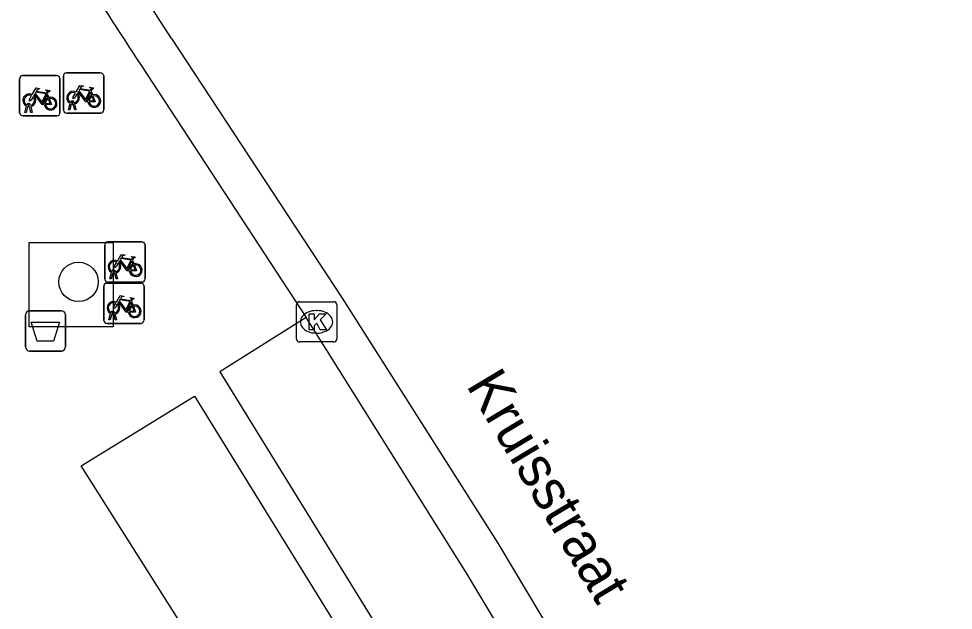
# Model space of a CAD drawing. Extents: x 160379 to 161131, y 383940 to 384849.
# Drawn here: x 161075.69 to 161098.92, y 384397.03 to 384411.72 of the extents above; entities that cross this region are included whole.
import ezdxf

# ---------------------------------------------------------------- set-up
doc = ezdxf.new("R2010")
doc.units = 0
for name, color, linetype in [('IMGEO_Afvalbak', 7, 'Continuous'), ('IMGEO_Boom', 7, 'Continuous'), ('IMGEO_Fietsenrek', 7, 'Continuous'), ('IMGEO_Fietspad_gesloten', 7, 'Continuous'), ('IMGEO_Fietspad_open', 7, 'Continuous'), ('IMGEO_Kolk', 7, 'Continuous'), ('IMGEO_Openbare_ruimte_label', 7, 'Continuous'), ('IMGEO_Voetpad_open', 7, 'Continuous')]:
    doc.layers.add(name, color=color, linetype=linetype)

msp = doc.modelspace()

# ---------------------------------------------------------------- linework, layer by layer
at = {"layer": 'IMGEO_Afvalbak'}
for p, q in [((161075.864, 384403.567), (161075.864, 384404.367)), ((161075.864, 384404.367), (161075.864, 384403.567)), ((161075.964, 384404.467), (161076.754, 384404.467)), ((161076.754, 384404.467), (161075.964, 384404.467)), ((161076.854, 384404.367), (161076.854, 384403.567)), ((161076.854, 384403.567), (161076.854, 384404.367)), ((161076.754, 384403.467), (161075.964, 384403.467)), ((161075.964, 384403.467), (161076.754, 384403.467))]:
    msp.add_line(p, q, dxfattribs=at)
msp.add_lwpolyline([(161076.007, 384404.181), (161076.711, 384404.181), (161076.562, 384403.711), (161076.156, 384403.711), (161076.007, 384404.181)], dxfattribs=at)
for centre, start, end in [((161075.964, 384404.367), 90, 180), ((161075.964, 384404.367), 90, 180), ((161076.754, 384404.367), 0, 90), ((161076.754, 384404.367), 360, 90), ((161075.964, 384403.567), 180, 270), ((161075.964, 384403.567), 180, 270), ((161076.754, 384403.567), 270, 0), ((161076.754, 384403.567), 270, 0)]:
    msp.add_arc(centre, 0.1, start, end, dxfattribs=at)
at = {"layer": 'IMGEO_Boom'}
msp.add_circle((161077.181, 384405.182), 0.489, dxfattribs=at)
at = {"layer": 'IMGEO_Fietsenrek'}
for p, q in [((161075.718, 384409.384), (161075.718, 384410.225)), ((161075.718, 384410.225), (161075.718, 384409.384)), ((161075.793, 384410.309), (161076.634, 384410.309)), ((161076.634, 384410.309), (161075.793, 384410.309)), ((161076.718, 384410.234), (161076.718, 384409.393)), ((161076.718, 384409.393), (161076.718, 384410.234)), ((161076.806, 384409.449), (161076.806, 384410.29)), ((161076.806, 384410.29), (161076.806, 384409.449)), ((161076.881, 384410.374), (161077.722, 384410.374)), ((161077.722, 384410.374), (161076.881, 384410.374)), ((161077.806, 384410.299), (161077.806, 384409.458)), ((161077.806, 384409.458), (161077.806, 384410.299)), ((161077.493, 384409.923), (161077.529, 384409.828)), ((161076.405, 384409.858), (161076.441, 384409.763)), ((161075.845, 384409.393), (161075.884, 384409.553)), ((161075.914, 384409.541), (161075.879, 384409.393)), ((161075.956, 384409.565), (161075.955, 384409.569)), ((161075.997, 384409.393), (161075.963, 384409.535)), ((161075.987, 384409.576), (161075.988, 384409.569)), ((161075.995, 384409.539), (161076.03, 384409.393)), ((161076.933, 384409.458), (161076.972, 384409.618)), ((161076.967, 384409.458), (161076.933, 384409.458)), ((161077.002, 384409.606), (161076.967, 384409.458)), ((161077.044, 384409.63), (161077.043, 384409.634)), ((161077.085, 384409.458), (161077.051, 384409.6)), ((161077.075, 384409.641), (161077.076, 384409.634)), ((161077.083, 384409.604), (161077.118, 384409.458)), ((161077.118, 384409.458), (161077.085, 384409.458)), ((161076.643, 384409.309), (161075.802, 384409.309)), ((161075.802, 384409.309), (161076.643, 384409.309)), ((161075.879, 384409.393), (161075.845, 384409.393)), ((161076.03, 384409.393), (161075.997, 384409.393)), ((161077.731, 384409.374), (161076.89, 384409.374)), ((161076.89, 384409.374), (161077.731, 384409.374)), ((161077.834, 384405.251), (161077.834, 384406.092)), ((161077.834, 384406.092), (161077.834, 384405.251)), ((161077.909, 384406.176), (161078.75, 384406.176)), ((161078.75, 384406.176), (161077.909, 384406.176)), ((161078.834, 384406.101), (161078.834, 384405.26)), ((161078.834, 384405.26), (161078.834, 384406.101)), ((161078.521, 384405.725), (161078.557, 384405.63)), ((161077.961, 384405.26), (161078, 384405.42)), ((161078.03, 384405.408), (161077.995, 384405.26)), ((161078.072, 384405.432), (161078.071, 384405.436)), ((161078.113, 384405.26), (161078.079, 384405.402)), ((161078.103, 384405.443), (161078.104, 384405.436)), ((161078.111, 384405.406), (161078.146, 384405.26)), ((161077.809, 384404.228), (161077.809, 384405.069)), ((161077.809, 384405.069), (161077.809, 384404.228)), ((161077.884, 384405.153), (161078.725, 384405.153)), ((161078.725, 384405.153), (161077.884, 384405.153)), ((161078.759, 384405.176), (161077.918, 384405.176)), ((161077.918, 384405.176), (161078.759, 384405.176)), ((161077.995, 384405.26), (161077.961, 384405.26)), ((161078.146, 384405.26), (161078.113, 384405.26)), ((161078.809, 384405.078), (161078.809, 384404.237)), ((161078.809, 384404.237), (161078.809, 384405.078)), ((161078.496, 384404.702), (161078.532, 384404.607)), ((161077.936, 384404.237), (161077.975, 384404.397)), ((161078.005, 384404.385), (161077.97, 384404.237)), ((161078.047, 384404.409), (161078.046, 384404.413)), ((161078.088, 384404.237), (161078.054, 384404.379)), ((161078.078, 384404.42), (161078.079, 384404.413)), ((161078.086, 384404.383), (161078.121, 384404.237)), ((161078.734, 384404.153), (161077.893, 384404.153)), ((161077.893, 384404.153), (161078.734, 384404.153)), ((161077.97, 384404.237), (161077.936, 384404.237)), ((161078.121, 384404.237), (161078.088, 384404.237))]:
    msp.add_line(p, q, dxfattribs=at)
for points in [[(161076.031, 384409.835), (161076.126, 384409.999), (161076.212, 384409.985), (161076.214, 384409.976), (161076.158, 384409.965), (161076.131, 384409.92), (161076.387, 384409.879)], [(161076.387, 384409.879), (161076.412, 384409.928), (161076.406, 384409.932), (161076.383, 384409.936), (161076.371, 384409.943), (161076.37, 384409.946), (161076.372, 384409.951), (161076.467, 384409.936), (161076.469, 384409.926), (161076.459, 384409.913), (161076.447, 384409.907), (161076.433, 384409.913), (161076.405, 384409.858)], [(161077.119, 384409.9), (161077.214, 384410.064), (161077.3, 384410.05), (161077.302, 384410.041), (161077.246, 384410.03), (161077.219, 384409.985), (161077.475, 384409.944)], [(161077.462, 384409.919), (161077.205, 384409.96), (161077.188, 384409.931), (161077.355, 384409.711), (161077.462, 384409.919)], [(161077.475, 384409.944), (161077.5, 384409.993), (161077.494, 384409.997), (161077.471, 384410.001), (161077.459, 384410.008), (161077.458, 384410.011), (161077.46, 384410.016), (161077.555, 384410.001), (161077.557, 384409.991), (161077.547, 384409.978), (161077.535, 384409.972), (161077.521, 384409.978), (161077.493, 384409.923)], [(161076.052, 384409.783), (161076, 384409.693), (161075.96, 384409.668), (161075.961, 384409.715), (161076.016, 384409.809)], [(161076.327, 384409.591), (161076.277, 384409.591), (161076.086, 384409.842), (161076.067, 384409.81)], [(161076.374, 384409.854), (161076.117, 384409.895), (161076.1, 384409.866), (161076.267, 384409.646), (161076.374, 384409.854)], [(161076.422, 384409.756), (161076.392, 384409.833), (161076.283, 384409.615), (161076.326, 384409.615)], [(161076.356, 384409.615), (161076.476, 384409.614), (161076.432, 384409.728)], [(161076.452, 384409.735), (161076.507, 384409.59), (161076.357, 384409.59)], [(161077.14, 384409.848), (161077.088, 384409.758), (161077.048, 384409.733), (161077.049, 384409.78), (161077.104, 384409.874)], [(161077.415, 384409.656), (161077.365, 384409.656), (161077.174, 384409.907), (161077.155, 384409.875)], [(161077.51, 384409.821), (161077.48, 384409.898), (161077.371, 384409.68), (161077.414, 384409.68)], [(161077.444, 384409.68), (161077.564, 384409.679), (161077.52, 384409.793)], [(161077.54, 384409.8), (161077.595, 384409.655), (161077.445, 384409.655)], [(161078.147, 384405.702), (161078.242, 384405.866), (161078.328, 384405.852), (161078.33, 384405.843), (161078.274, 384405.832), (161078.247, 384405.787), (161078.503, 384405.746)], [(161078.49, 384405.721), (161078.233, 384405.762), (161078.216, 384405.733), (161078.383, 384405.513), (161078.49, 384405.721)], [(161078.503, 384405.746), (161078.528, 384405.795), (161078.522, 384405.799), (161078.499, 384405.803), (161078.487, 384405.81), (161078.486, 384405.813), (161078.488, 384405.818), (161078.583, 384405.803), (161078.585, 384405.793), (161078.575, 384405.78), (161078.563, 384405.774), (161078.549, 384405.78), (161078.521, 384405.725)], [(161078.168, 384405.65), (161078.116, 384405.56), (161078.076, 384405.535), (161078.077, 384405.582), (161078.132, 384405.676)], [(161078.443, 384405.458), (161078.393, 384405.458), (161078.202, 384405.709), (161078.183, 384405.677)], [(161078.538, 384405.623), (161078.508, 384405.7), (161078.399, 384405.482), (161078.442, 384405.482)], [(161078.472, 384405.482), (161078.592, 384405.481), (161078.548, 384405.595)], [(161078.568, 384405.602), (161078.623, 384405.457), (161078.473, 384405.457)], [(161078.122, 384404.679), (161078.217, 384404.843), (161078.303, 384404.829), (161078.305, 384404.82), (161078.249, 384404.809), (161078.222, 384404.764), (161078.478, 384404.723)], [(161078.143, 384404.627), (161078.091, 384404.537), (161078.051, 384404.512), (161078.052, 384404.559), (161078.107, 384404.653)], [(161078.418, 384404.435), (161078.368, 384404.435), (161078.177, 384404.686), (161078.158, 384404.654)], [(161078.465, 384404.698), (161078.208, 384404.739), (161078.191, 384404.71), (161078.358, 384404.49), (161078.465, 384404.698)], [(161078.513, 384404.6), (161078.483, 384404.677), (161078.374, 384404.459), (161078.417, 384404.459)], [(161078.543, 384404.579), (161078.598, 384404.434), (161078.448, 384404.434)], [(161078.478, 384404.723), (161078.503, 384404.772), (161078.497, 384404.776), (161078.474, 384404.78), (161078.462, 384404.787), (161078.461, 384404.79), (161078.463, 384404.795), (161078.558, 384404.78), (161078.56, 384404.77), (161078.55, 384404.757), (161078.538, 384404.751), (161078.524, 384404.757), (161078.496, 384404.702)], [(161078.447, 384404.459), (161078.567, 384404.458), (161078.523, 384404.572)]]:
    msp.add_lwpolyline(points, dxfattribs=at)
for centre, radius, start, end in [((161075.796, 384410.231), 0.0779, 92.4484, 184.2845), ((161075.796, 384410.231), 0.0779, 92.4484, 184.2845), ((161076.64, 384410.231), 0.0779, 2.4484, 94.2845), ((161076.64, 384410.231), 0.0779, 2.4484, 94.2845), ((161076.884, 384410.296), 0.0779, 92.4484, 184.2845), ((161076.884, 384410.296), 0.0779, 92.4484, 184.2845), ((161077.728, 384410.296), 0.0779, 2.4484, 94.2845), ((161077.728, 384410.296), 0.0779, 2.4484, 94.2845), ((161075.958, 384409.694), 0.159, 62.6766, 242.1369), ((161075.958, 384409.694), 0.129, 63.3192, 238.903), ((161075.958, 384409.694), 0.129, 283.6043, 43.4302), ((161075.958, 384409.694), 0.159, 283.5766, 46.6042), ((161076.485, 384409.61), 0.159, 113.3408, 178.3217), ((161076.485, 384409.61), 0.159, 187.0065, 105.7708), ((161076.485, 384409.61), 0.129, 113.923, 177.9556), ((161076.485, 384409.61), 0.129, 188.6715, 104.5883), ((161077.046, 384409.759), 0.159, 62.6766, 242.1369), ((161077.046, 384409.759), 0.129, 63.3192, 238.903), ((161077.046, 384409.759), 0.129, 283.6043, 43.4302), ((161077.046, 384409.759), 0.159, 283.5766, 46.6042), ((161077.573, 384409.675), 0.159, 113.3408, 178.3217), ((161077.573, 384409.675), 0.159, 187.0065, 105.7708), ((161077.573, 384409.675), 0.129, 113.923, 177.9556), ((161077.573, 384409.675), 0.129, 188.6715, 104.5883), ((161075.938, 384409.565), 0.0499, 12.8025, 158.6934), ((161075.958, 384409.694), 0.159, 253.9967, 271.7867), ((161075.938, 384409.565), 0.0174, 12.8025, 163.4502), ((161075.958, 384409.694), 0.129, 253.415, 269.0204), ((161077.026, 384409.63), 0.0499, 12.8025, 158.6934), ((161077.046, 384409.759), 0.159, 253.9967, 271.7867), ((161077.026, 384409.63), 0.0174, 12.8025, 163.4502), ((161077.046, 384409.759), 0.129, 253.415, 269.0204), ((161077.728, 384409.452), 0.0779, 272.4484, 4.2845), ((161077.728, 384409.452), 0.0779, 272.4484, 4.2845), ((161075.796, 384409.387), 0.0779, 182.4484, 274.2845), ((161075.796, 384409.387), 0.0779, 182.4484, 274.2845), ((161076.64, 384409.387), 0.0779, 272.4484, 4.2845), ((161076.64, 384409.387), 0.0779, 272.4484, 4.2845), ((161076.884, 384409.452), 0.0779, 182.4484, 274.2845), ((161076.884, 384409.452), 0.0779, 182.4484, 274.2845), ((161077.912, 384406.098), 0.0779, 92.4484, 184.2845), ((161077.912, 384406.098), 0.0779, 92.4484, 184.2845), ((161078.756, 384406.098), 0.0779, 2.4484, 94.2845), ((161078.756, 384406.098), 0.0779, 2.4484, 94.2845), ((161078.074, 384405.561), 0.159, 62.6766, 242.1369), ((161078.074, 384405.561), 0.129, 63.3192, 238.903), ((161078.074, 384405.561), 0.129, 283.6043, 43.4302), ((161078.074, 384405.561), 0.159, 283.5766, 46.6042), ((161078.601, 384405.477), 0.159, 113.3408, 178.3217), ((161078.601, 384405.477), 0.159, 187.0065, 105.7708), ((161078.601, 384405.477), 0.129, 113.923, 177.9556), ((161078.601, 384405.477), 0.129, 188.6715, 104.5883), ((161078.054, 384405.432), 0.0499, 12.8025, 158.6934), ((161078.074, 384405.561), 0.159, 253.9967, 271.7867), ((161078.054, 384405.432), 0.0174, 12.8025, 163.4502), ((161078.074, 384405.561), 0.129, 253.415, 269.0204), ((161077.887, 384405.075), 0.0779, 92.4484, 184.2845), ((161077.887, 384405.075), 0.0779, 92.4484, 184.2845), ((161077.912, 384405.254), 0.0779, 182.4484, 274.2845), ((161077.912, 384405.254), 0.0779, 182.4484, 274.2845), ((161078.731, 384405.075), 0.0779, 2.4484, 94.2845), ((161078.731, 384405.075), 0.0779, 2.4484, 94.2845), ((161078.756, 384405.254), 0.0779, 272.4484, 4.2845), ((161078.756, 384405.254), 0.0779, 272.4484, 4.2845), ((161078.049, 384404.538), 0.159, 62.6766, 242.1369), ((161078.049, 384404.538), 0.129, 63.3192, 238.903), ((161078.049, 384404.538), 0.129, 283.6043, 43.4302), ((161078.049, 384404.538), 0.159, 283.5766, 46.6042), ((161078.576, 384404.454), 0.159, 113.3408, 178.3217), ((161078.576, 384404.454), 0.159, 187.0065, 105.7708), ((161078.576, 384404.454), 0.129, 188.6715, 104.5883), ((161078.029, 384404.409), 0.0499, 12.8025, 158.6934), ((161078.049, 384404.538), 0.159, 253.9967, 271.7867), ((161078.029, 384404.409), 0.0174, 12.8025, 163.4502), ((161078.049, 384404.538), 0.129, 253.415, 269.0204), ((161078.576, 384404.454), 0.129, 113.923, 177.9556), ((161077.887, 384404.231), 0.0779, 182.4484, 274.2845), ((161077.887, 384404.231), 0.0779, 182.4484, 274.2845), ((161078.731, 384404.231), 0.0779, 272.4484, 4.2845), ((161078.731, 384404.231), 0.0779, 272.4484, 4.2845)]:
    msp.add_arc(centre, radius, start, end, dxfattribs=at)
at = {"layer": 'IMGEO_Fietspad_gesloten'}
msp.add_lwpolyline([(161079.487, 384411.231), (161083.732, 384404.781), (161087.596, 384398.692), (161098.918, 384379.758)], dxfattribs=at)
msp.add_arc((161359.877, 384595.329), 335.426, 210.52244, 213.28799, dxfattribs=at)
at = {"layer": 'IMGEO_Fietspad_open'}
for points in [[(161078.727, 384410.572), (161082.836, 384404.298)], [(161088.726, 384394.782), (161086.839, 384397.924), (161083.315, 384403.535), (161082.836, 384404.298)]]:
    msp.add_lwpolyline(points, dxfattribs=at)
msp.add_arc((161390.219, 384613.83), 371.943, 212.81315, 213.12566, dxfattribs=at)
at = {"layer": 'IMGEO_Kolk'}
for p, q in [((161082.595, 384403.765), (161082.595, 384404.617)), ((161082.67, 384404.691), (161083.522, 384404.691)), ((161083.596, 384404.617), (161083.596, 384403.765)), ((161083.083, 384404.471), (161083.108, 384404.471)), ((161083.106, 384403.911), (161083.081, 384403.911)), ((161083.522, 384403.691), (161082.67, 384403.691))]:
    msp.add_line(p, q, dxfattribs=at)
for points in [[(161082.595, 384403.765), (161082.595, 384404.617)], [(161082.67, 384404.691), (161083.522, 384404.691)], [(161083.596, 384404.617), (161083.596, 384403.765)], [(161082.916, 384404.391), (161083.039, 384404.391), (161083.039, 384404.24), (161083.169, 384404.391), (161083.333, 384404.391), (161083.187, 384404.24), (161083.34, 384403.991), (161083.188, 384403.991), (161083.103, 384404.155), (161083.039, 384404.088), (161083.039, 384403.991), (161082.916, 384403.991), (161082.916, 384404.391)], [(161083.522, 384403.691), (161082.67, 384403.691)]]:
    msp.add_lwpolyline(points, dxfattribs=at)
for centre, start, end in [((161082.672, 384404.615), 91.552, 178.448), ((161082.672, 384404.615), 91.552, 178.448), ((161083.52, 384404.615), 1.552, 88.448), ((161083.52, 384404.615), 1.552, 88.448), ((161082.672, 384403.767), 181.552, 268.448), ((161082.672, 384403.767), 181.552, 268.448), ((161083.52, 384403.767), 271.552, 358.448), ((161083.52, 384403.767), 271.552, 358.448)]:
    msp.add_arc(centre, 0.0765, start, end, dxfattribs=at)
for centre, major_axis, ratio, start_param, end_param in [((161083.082, 384404.191), (-0.387, 0.002), 0.722429, 4.712389, 7.853982), ((161083.107, 384404.191), (-0.39, 0.002), 0.717154, 1.570796, 4.712389)]:
    msp.add_ellipse(centre, major_axis=major_axis, ratio=ratio, start_param=start_param, end_param=end_param, dxfattribs=at)
at = {"layer": 'IMGEO_Voetpad_open'}
for points in [[(161078.043, 384406.16), (161078.043, 384404.068), (161075.951, 384404.068), (161075.954, 384406.16), (161078.043, 384406.16)], [(161082.836, 384404.298), (161080.691, 384402.946), (161086.524, 384393.501), (161088.726, 384394.782)], [(161082.799, 384391.851), (161077.247, 384400.615), (161080.059, 384402.345), (161085.515, 384393.528), (161082.799, 384391.851)]]:
    msp.add_lwpolyline(points, dxfattribs=at)

# ---------------------------------------------------------------- texts
at = {"layer": 'IMGEO_Openbare_ruimte_label'}
msp.add_text('Kruisstraat', height=1, rotation=300.9245, dxfattribs=at).set_placement((161086.799, 384402.616))

doc.saveas('drawing.dxf')
